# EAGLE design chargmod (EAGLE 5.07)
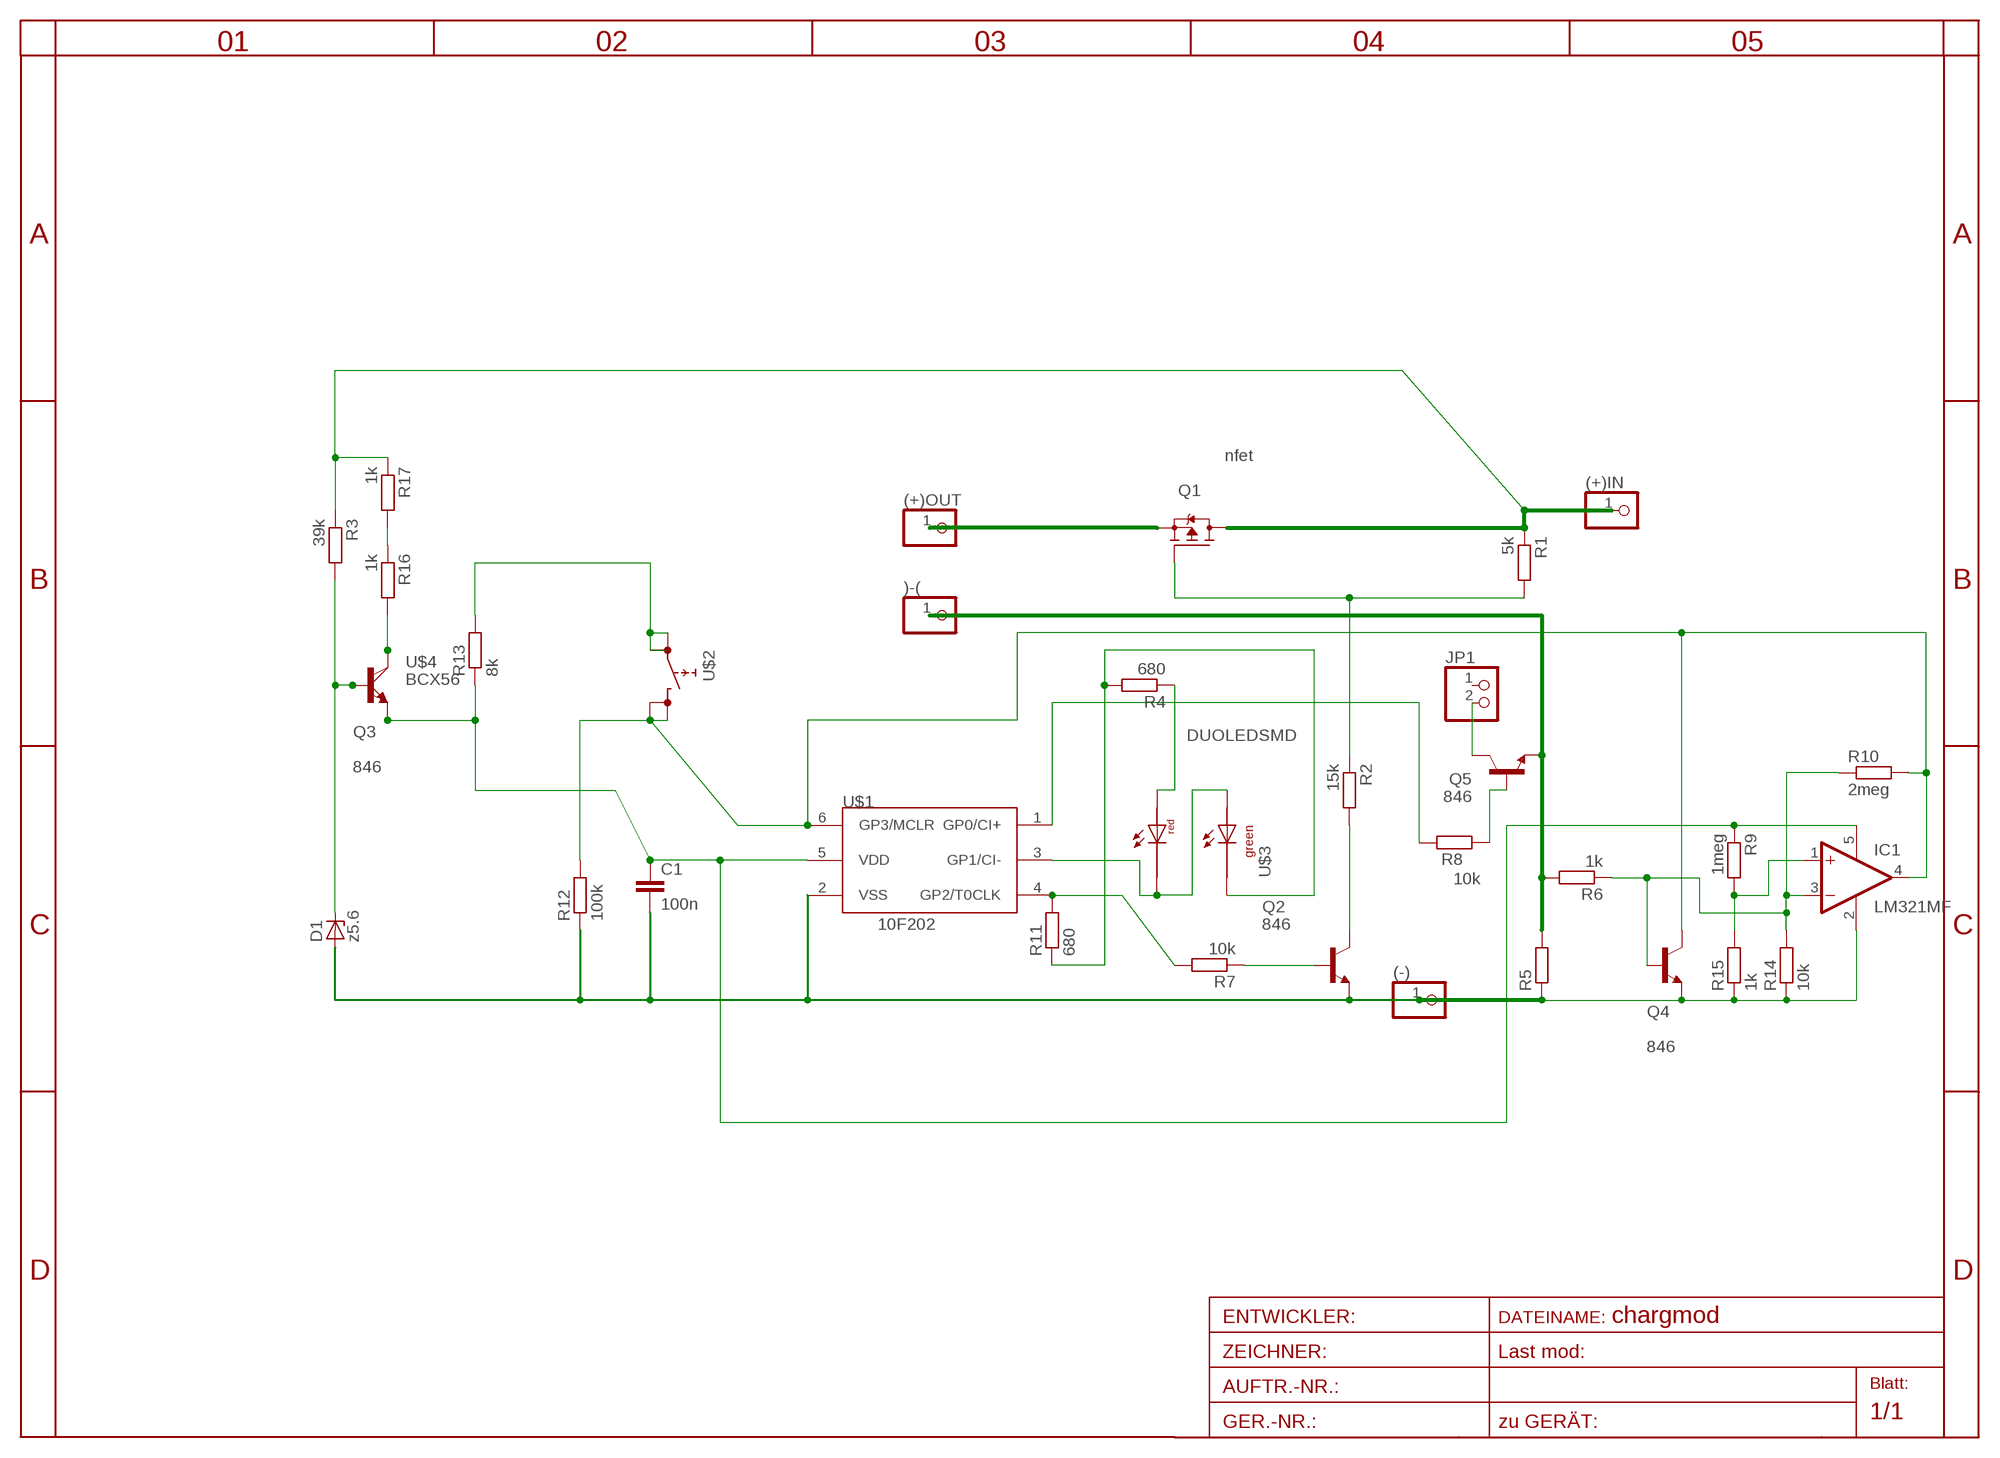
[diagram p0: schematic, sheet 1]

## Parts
(+)IN  PINHD-1X11MM6  [1X1MM8]
(+)OUT  PINHD-1X11MM6  [1X1MM8]
(-)  PINHD-1X11MM6  [1X1MM8]
)-(  PINHD-1X11MM6  [1X1MM8]
C1  100n  C-EUC1206  [C1206]
D1  z5.6  ZENER-DIODESOD80C  [SOD80C]
IC1  LM321MF  [SOT23-5]
JP1  PINHD-1X2  [1X02]
Q1  nfet  FDD4141TO252  [TO252]
Q2  846  BC846BSMD  [SOT23]
Q3  846  BC846BSMD  [SOT23]
Q4  846  BC846BSMD  [SOT23]
Q5  846  BC846BSMD  [SOT23]
R1  5k  R-EU_R0805  [R0805]
R2  15k  R-EU_R0805  [R0805]
R3  39k  R-EU_R0805  [R0805]
R4  680  R-EU_R0805  [R0805]
R5  R-EU_0207/10  [0207/10]
R6  1k  R-EU_R1206  [R1206]
R7  10k  R-EU_R1206  [R1206]
R8  10k  R-EU_R0805  [R0805]
R9  1meg  R-EU_R0805  [R0805]
R10  2meg  R-EU_R0805  [R0805]
R11  680  R-EU_R0805  [R0805]
R12  100k  R-EU_R0805  [R0805]
R13  8k  R-EU_R0805  [R0805]
R14  10k  R-EU_R0805  [R0805]
R15  1k  R-EU_R0805  [R0805]
R16  1k  R-EU_R1206  [R1206]
R17  1k  R-EU_R1206  [R1206]
U$1  10F202  PIC10F202OT  [SOT23-6]
U$2  SMD4  [SMD4]
U$3  DUOLEDSMD  [DUOLEDSMD]
U$4  BCX56  [SOT223]

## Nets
+OUT: )-(.1 Q5.2(E) R5.2 R6.2
GP2: R7.2 R11.2 U$1.4(GP2/T0CLK)
GP3: IC1.4(OUT) Q4.3(C) R10.2 R12.2 U$1.6(GP3/MCLR) U$2.3(2.1) U$2.4(2.2)
N$2: U$1.3(GP1/CI-) U$3.AGRN U$3.CRED
N$3: Q2.3(C) R2.2
N$4: D1.C Q3.1(B) R3.2 U$4.1(B)
N$5: R4.1 U$3.ARED
N$6: R4.2 R11.1 U$3.CGRN
N$7: Q1.1(G) R1.2 R2.1
N$8: Q3.3(C) R16.2 U$4.2(C)
N$9: IC1.3(-IN) Q4.1(B) R6.1 R10.1 R14.2
N$10: Q2.1(B) R7.1
N$11: JP1.2 Q5.3(C)
N$12: R8.2 U$1.1(GP0/CI+)
N$13: Q5.1(B) R8.1
N$14: R16.1 R17.2
N$15: R13.2 U$2.1(1.1) U$2.2(1.2)
N$16: IC1.1(+IN) R9.2 R15.2
V+IN: (+)IN.1 Q1.2(D) R1.1 R3.1 R17.1
V+OUT: (+)OUT.1 Q1.3(S)
VDD: C1.1 IC1.5(V+) Q3.2(E) R9.1 R13.1 U$1.5(VDD) U$4.3(E)
VSS: (-).1 C1.2 D1.A IC1.2(V-) Q2.2(E) Q4.2(E) R5.1 R12.1 R14.1 R15.1 U$1.2(VSS)
Unconnected: JP1.1

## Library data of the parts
(+)IN (+)OUT (-) )-( = pinhead:PINHD-1X1: PIN HEADER
C1 = rcl:C-EU: CAPACITOR, European symbol
D1 = diode-1:ZENER-DIODE: Z-Diode
IC1 = linear:LM321?*: Low Power Single Op Amp Source: http://cache.national.com/ds/LM/LM321.pdf
JP1 = pinhead(2):PINHD-1X2: PIN HEADER
Q1 = transistor-fet:FDD4141: P-Channel PowerTrench® MOSFET Source: FDD4141.pdf
Q2-Q5 = transistor-npn:BC846*: NPN Transistor
R1-R17 = rcl:R-EU_: RESISTOR, European symbol
U$1 = microchip-5:PIC10F2*: uPC nW 0,25/0,5k Program Flash memory Comparator
U$2 = switch:SMD4
U$3 = led:DUOLEDSMD
U$4 = transistor-power:BCX56

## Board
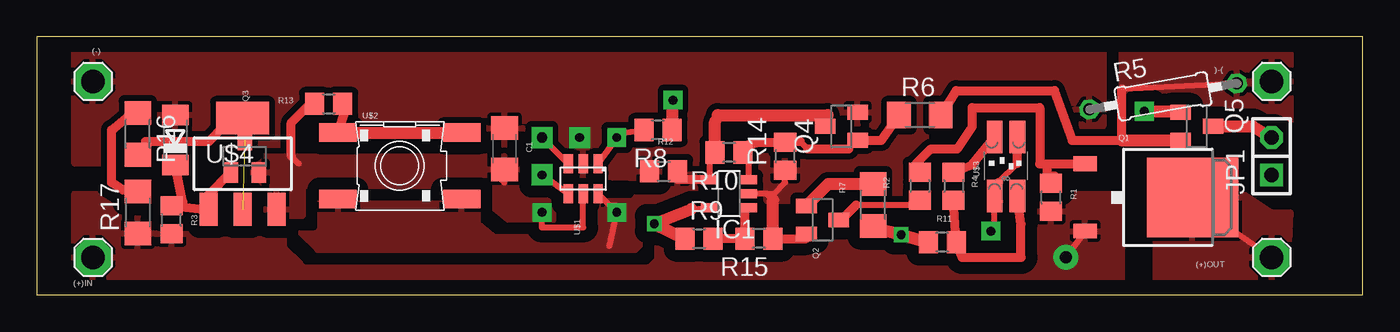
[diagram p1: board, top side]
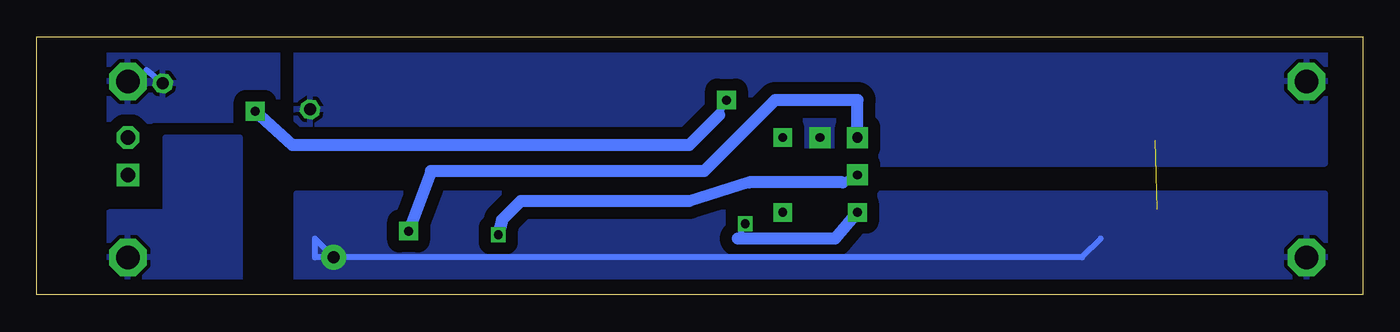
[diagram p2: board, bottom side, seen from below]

Size 90 x 17.5 mm. Coordinates in mm from the lower left corner, seen from the top.
Outline: 0,0 90,0 90,17.5 0,17.5 0,0
Copper layers (1*16): Top 0.035mm / dielectric 1.5mm / Bottom 0.035mm
Design rules "default *": minimum track width 10mil, minimum drill 14mil, track to track 8mil, track to pad 8mil, pad to pad 8mil, via to via 8mil, smd to smd 8mil, copper to edge 40mil, drill to drill 8mil, minimum pad ring 10mil, minimum via ring 8mil, stop-mask expansion 4mil, vias tented up to drill 0mil, thermal gap 10mil

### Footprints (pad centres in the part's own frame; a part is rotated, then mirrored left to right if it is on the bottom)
1X1MM8 = drill 1.6 pad 2.54 octagon: 1 0,0
C1206 = smd 1.6 x 1.8: 1 -1.4,0; 2 1.4,0
SOD80C = smd 1.4 x 1.8: A 1.7,0; C -1.7,0
SOT23-5 = smd 0.6 x 1.2: 1 -0.95,-1.306; 2 0,-1.306; 3 0.95,-1.306; 4 0.95,1.306; 5 -0.95,1.306
1X02 = drill 1 pad 1.27 square: 1 -1.27,0 | drill 1 pad 1.27 octagon: 2 1.27,0
TO252 = smd 1 x 1.6: 1 -2.28,-4.8; 2 2.28,-4.8 | smd 5.4 x 6.2: 3 0,2.5
SOT23 = smd 1 x 1.4: 1 -0.95,-1.1; 2 0.95,-1.1; 3 0,1.1
R0805 = smd 1.3 x 1.5: 1 -0.95,0; 2 0.95,0
0207/10 = drill 0.813 octagon: 1 -5.08,0; 2 5.08,0
R1206 = smd 1.6 x 1.803: 1 -1.422,0; 2 1.422,0
SOT23-6 = smd 0.635 x 1.27: 1 -1.016,-1.016; 2 0,-1.016; 3 1.016,-1.016; 4 1.016,1.016; 5 0,1.016; 6 -1.016,1.016
SMD4 = smd 2.54 x 1.27: 1 -4.2,2.25; 2 4.2,2.25; 3 -4.2,-2.25; 4 4.2,-2.25
DUOLEDSMD = smd 1.067 x 2.184: AGRN 0.77,1.95; ARED -0.77,1.95; CGRN 0.77,-2.05; CRED -0.77,-2.05
SOT223 = smd 1.219 x 2.235: 1 -2.311,-3.099; 2 0,-3.099; 3 2.311,-3.099 | smd 3.6 x 2.2: 4 0,3.099

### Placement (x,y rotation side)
(+)IN  3.81,2.54 0 top
(+)OUT  83.82,2.54 0 top
(-)  3.81,14.48 0 top
)-(  83.82,14.48 0 top
C1  31.75,9.91 90 top
D1  9.4,10.51 90 top
IC1  46.99,6.86 90 top
JP1  83.82,9.4 90 top
Q1  75.95,6.6 270 top
Q2  53.34,5.08 270 top
Q3  14.12,9.4 0 top
Q4  54.61,11.43 90 top
Q5  78.74,11.43 270 top
R1  68.83,6.6 90 top
R2  59.94,7.37 270 top
R3  9.14,5.08 90 top
R4  62.23,7.37 270 top
R5  76.45,13.46 10 top
R6  59.94,12.19 0 top
R7  56.77,6.1 270 top
R8  42.16,11.18 180 top
R9  44.96,3.81 0 top
R10  46.99,9.65 180 top
R11  61.47,3.56 180 top
R12  42.55,8.38 0 top
R13  19.81,12.95 0 top
R14  50.8,9.4 90 top
R15  49.02,3.81 180 top
R16  6.86,10.92 270 top
R17  6.86,5.59 90 top
U$1  37.08,7.87 180 top
U$2  24.64,8.75 0 top
U$3  65.79,8.75 0 top
U$4  13.97,8.89 0 top

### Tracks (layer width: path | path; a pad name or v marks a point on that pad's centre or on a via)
+OUT
  Top 0.406: 73.66,13.97 R5.2
  Top 0.61: R6.2 62.42,13.84 69.09,13.84 70.29,10.48 73.66,10.48 73.66,13.97
  Top 0.813: 73.66,10.48 Q5.2
  Bottom 0.406: )-(.1 83.31,14.48 82.55,15.24 R5.2
  pour Top (isolate 0.813, rank 4): 73.66,16.51 85.09,16.51 85.09,11.43 73.66,11.43
  pour Bottom (isolate 0.813, rank 4): 73.66,16.51 85.09,16.51 85.09,11.43 73.66,11.43
GP2  (via drill 0.6, 0.6 pad 1.42)
  Top 0.406: U$1.4 v34.29,8.13 | R7.2 56.16,4.32 57.66,4.32
  Top 0.813: 57.66,4.32 v58.67,4.06 R11.2
  Bottom 0.406: 35.31,7.62 34.54,8.13 v34.29,8.13 34.29,7.87
  Bottom 0.813: 35.31,7.62 41.66,7.62 45.72,6.35 57.15,6.35 58.42,5.08 v58.67,4.06
GP3  (via drill 0.6 pad 1.27)
  Top 0.406: U$1.6 38.92,6.04 39.37,6.04 v39.37,5.59 38.86,3.3 | IC1.4 45.68,9.3 R10.2 | 46.04,11.75 46.23,12.19 | 53.68,12.19 Q4.3
  Top 0.61: IC1.4 43.49,7.81 R12.2
  Top 0.813: R10.2 46.04,11.75 | 46.23,12.19 53.68,12.19
  pour Top (isolate 0.813, rank 2): 17.78,5.59 17.78,4.32 19.05,3.05 40.64,3.05 45.47,7.87 45.21,8.13 43.18,8.13 41.91,6.86 40.89,6.86 40.39,6.35 38.61,6.35 36.83,4.32 31.75,4.32 29.21,6.86 19.05,6.86
N$2  (via drill 0.6 pad 1.27, 0.7 pad 1.42)
  Top 0.406: U$1.3 v34.29,10.67 | 65.28,7.62 66.56,8.9 | v64.77,4.32 65.02,4.83 U$3.CRED 65.28,6.34
  Top 0.61: 66.56,8.9 U$3.AGRN | 65.28,6.34 65.28,7.62
  Bottom 0.813: v34.29,10.67 34.29,13.21 39.88,13.21 44.7,8.38 63.25,8.38 v64.77,4.32
N$3
  Top 0.406: 54.53,5 Q2.3 | 55.63,6.1 59.12,6.1 R2.2
  Top 0.61: 54.53,5 55.63,6.1
N$4
  Top 0.406: R3.2 9.91,6.28 | 11.64,5.78 U$4.1 11.66,6.79
  Top 0.61: 9.91,6.28 D1.C | R3.2 11.64,5.78 | 11.66,6.79 Q3.1
N$5
  Top 0.61: U$3.ARED 63.48,8.81 R4.1
N$6
  Top 0.406: R11.1 62.36,4.26
  Top 0.61: R11.1 62.8,2.54 66.8,2.54 66.8,4.8 U$3.CGRN | 62.36,4.26 R4.2
N$7
  Top 0.406: R2.1 59.69,8.89
  Top 0.61: 59.69,8.89 60.71,9.91 62.48,9.91 63.5,11.43 63.5,12.7 68.07,12.7 68.07,8.88 68.58,8.88 | R1.2 69.09,8.06 68.58,8.06 68.58,8.88 | 68.58,8.88 Q1.1
N$8  (1 unrouted)
  Top 0.406: R16.2 7.37,10.41 | 12.7,11.43 13.97,11.43 13.97,10.65 Q3.3
  Top 0.61: 7.37,10.41 11.68,10.41 12.7,11.43
N$9
  Top 0.406: IC1.3 48.3,9.3 R10.1 48.26,9.97 48.26,10.16 | Q4.1 55.69,10.48 55.12,9.91 | 51.82,10.41 52.32,9.91 | R14.2 50.36,10.41
  Top 0.61: R14.2 48.96,10.35 48.26,10.16 | 52.32,9.91 55.12,9.91 | 50.36,10.41 51.82,10.41 | Q4.1 57.32,10.48 R6.1
N$10
  Top 0.813: R7.1 53.72,7.52 Q2.1
N$11
  Top 0.813: Q5.3 82.55,11.43 JP1.2
N$12  (via drill 0.6 pad 1.27)
  Top 0.406: U$1.1 v39.37,10.67 39.69,10.99 R8.2
N$13  (via drill 0.6 pad 1.27)
  Top 0.813: R8.1 v43.18,13.21 | v75.18,12.45 77.57,12.45 Q5.1
  Bottom 0.406: v43.18,13.21 43.69,12.19
  Bottom 0.813: 43.69,12.19 45.72,10.16 72.64,10.16 v75.18,12.45
N$14
  Top 0.406: 6.5,12.34 R16.1 | R17.2 7.01,7.11
  Top 0.61: 6.5,12.34 5.08,11.18 5.08,7.62 5.84,7.11 7.01,7.11
N$15
  Top 0.406: 20.83,12.7 20.64,12.7 R13.2
  Top 0.61: U$2.1 20.95,12.56 20.83,12.7
  Top 0.813: U$2.1 U$2.2
N$16
  Top 0.406: 48.07,5.68 IC1.1
  Top 0.61: R9.2 R15.2 48.07,5.68
V+IN  (via drill 0.8 pad 1.68)
  Top 0.406: Q1.2 71.4,4.6 v69.85,2.54 | R1.1 69.31,5.4
  Bottom 0.406: 17.78,3.81 19.05,2.54 71.12,2.54 71.12,3.81 v69.85,2.54
  pour Top (isolate 0.813, rank 5): 2.54,6.86 73.66,6.86 73.66,0.51 2.54,0.51
  pour Top: 73.66,5.59 73.66,3.05 69.85,3.05 69.85,4.32 71.12,5.59
  pour Bottom (isolate 0.813, rank 5): 2.54,6.86 72.39,6.86 72.39,0.51 2.54,0.51
V+OUT
  Top 0.406: 81.28,4.32 (+)OUT.1 | 78.74,6.86 78.74,8.09 Q1.3
  pour Bottom: 81.28,5.59 85.09,5.59 85.09,0.51 76.2,0.51 76.2,10.67 81.28,10.67
  pour Top: 83.82,5.59 85.09,5.59 84.84,0.76 75.95,0.76 75.95,6.86 77.47,8.13 80.01,8.13
VDD  (via drill 0.6, 0.6 pad 1.27)
  Top 0.406: v34.29,5.59 34.29,4.57 37.08,4.57 U$1.5 | 44.41,5.81 IC1.5 | 31.75,7.62 31.5,7.87 | 18.29,12.7 R13.1 | 17.27,9.4 17.78,8.89
  Top 0.61: 18.29,12.7 17.27,11.68 17.27,9.4
  Top 0.813: 44.41,5.81 v41.91,4.83 R9.1
  Bottom 0.406: 42.42,3.81 v41.91,4.83
  Bottom 0.813: 42.42,3.81 35.81,3.81 v34.29,5.59
  pour Top (isolate 0.813): 13.97,8.13 15.24,9.4 31.75,9.4 34.29,6.86 35.05,6.35 35.05,5.08 32,5.08 29.21,7.37 18.03,7.37 18.03,5.33 13.97,5.33 13.72,5.59
VSS  (via drill 0.6 pad 1.42)
  Top 0.406: 49.53,6.86 IC1.2 | 49.53,6.86 50.04,6.86 50.8,7.62 R14.1 | 49.97,6.42 49.53,6.86 | 52.24,3.81 Q2.2
  Top 0.61: R15.1 52.24,3.81
  Top 0.813: R15.1 49.97,6.42
  other vias: 36.83,10.67
  pour Top (isolate 0.406, rank 5): 6.35,8.89 2.54,8.89 2.54,16.51 72.39,16.51 72.39,11.43 69.09,11.43 68.33,10.67 68.58,6.35 49.53,6.35 49.53,7.62
  pour Bottom (isolate 0.813, rank 5): 33.02,8.89 2.54,8.89 2.54,16.51 72.39,16.51 72.39,8.89 55.88,8.89 49.53,10.16 34.29,10.16 33.02,11.43

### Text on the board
tTest: 500u | 5u | 2m | 5m | 2m | 500u | 1m | 500u | 5m
Document: vin-10/2m | Vin*1k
